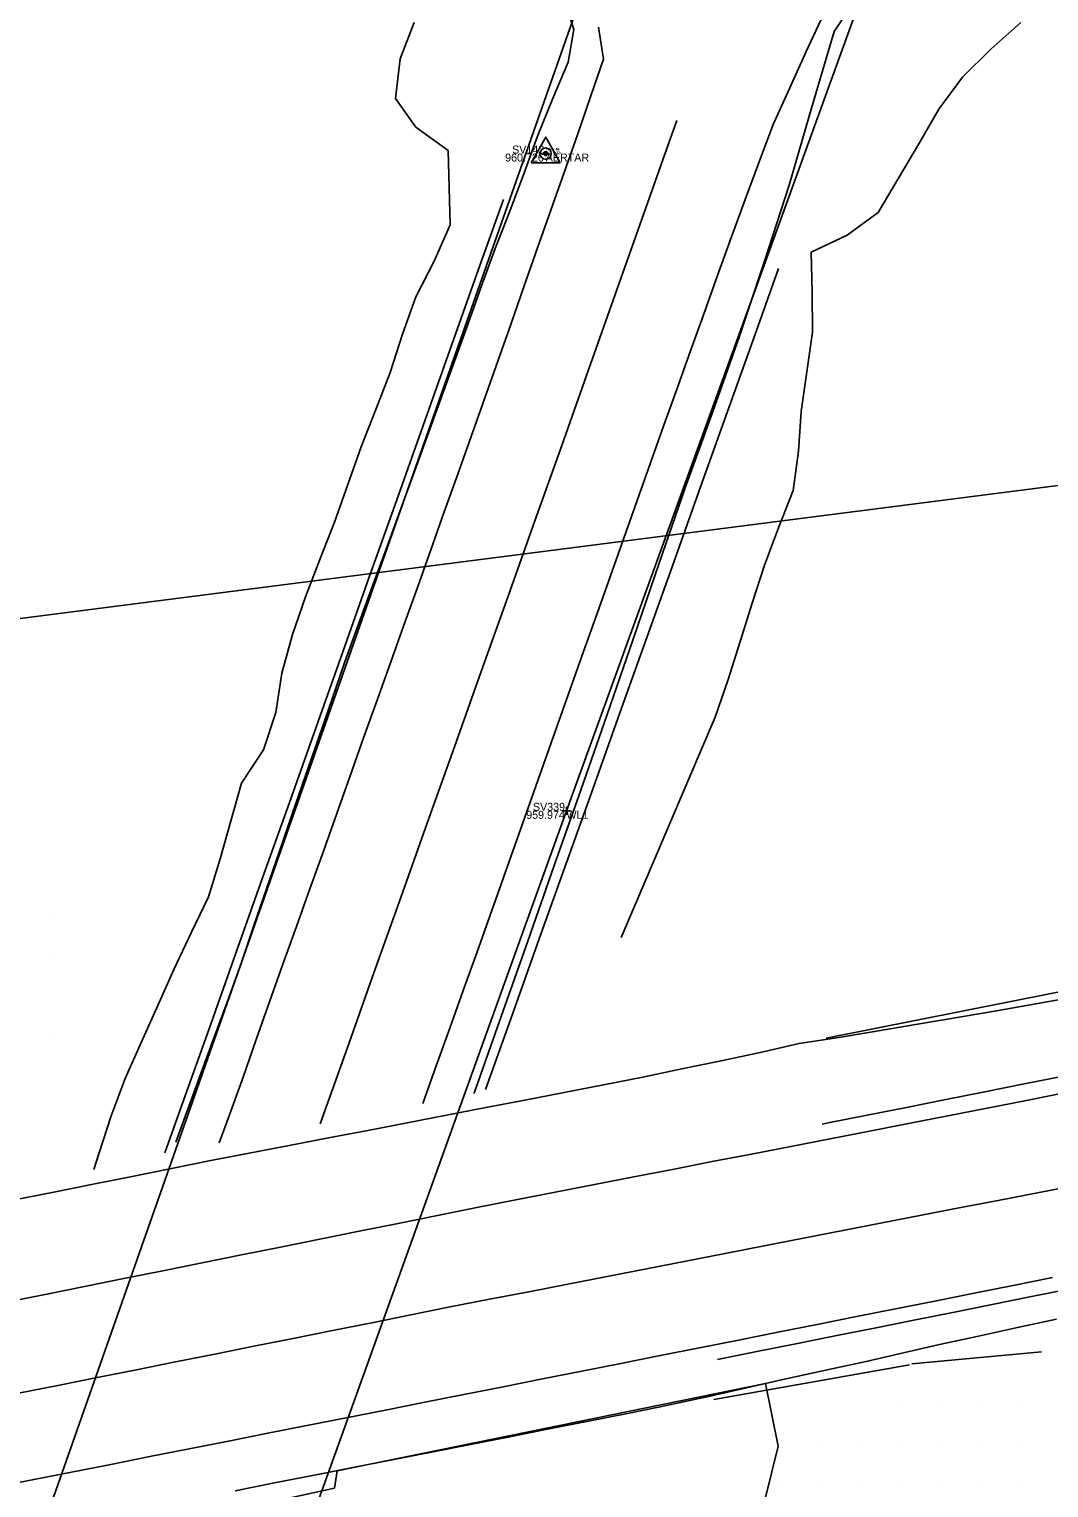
# Model space of a CAD drawing. Extents: x 2262025 to 2264532, y 740981 to 742724.
# Drawn here: x 2263228.5 to 2263355.9, y 742163 to 742345.3 of the extents above; entities that cross this region are included whole.
import ezdxf

# ---------------------------------------------------------------- set-up
doc = ezdxf.new("R2010")
doc.units = 0
for name, color, linetype in [('DT_X_Void', 7, 'Continuous'), ('GE_X_Alignment_1000_Curve_Data', 7, 'Continuous'), ('GE_X_Alignment_100_Bearings', 7, 'Continuous'), ('GE_X_Alignment_100_Cardinal_Points', 7, 'Continuous'), ('GE_X_Alignment_100_Curve_Data', 7, 'Continuous'), ('Ground Shots', 7, 'Continuous'), ('HY_X_Spring_Cells', 7, 'Continuous'), ('RW_X_CL', 7, 'Continuous'), ('RW_X_CL_1000_Bearings', 7, 'Continuous'), ('RW_X_CL_1000_Distances', 7, 'Continuous'), ('RW_X_CL_1000_Stations', 7, 'Continuous'), ('RW_X_CL_100_Cardinal_Points', 7, 'Continuous'), ('RW_X_CL_500_Stations', 7, 'Continuous'), ('SC_Scratch2', 7, 'Continuous'), ('SC_Scratch4', 7, 'Continuous'), ('SV_X_Control_Cells_Found', 7, 'Continuous'), ('SV_X_Text_Comment', 7, 'Continuous'), ('UT_X_Gas', 7, 'Continuous'), ('UT_X_Water', 7, 'Continuous')]:
    doc.layers.add(name, color=color, linetype=linetype)

msp = doc.modelspace()

# ---------------------------------------------------------------- linework, layer by layer
at = {"layer": 'DT_X_Void'}
msp.add_lwpolyline([(2263307.26, 742103.15), (2263312.47, 742108.54), (2263312.43, 742128.22), (2263317.18, 742148.27), (2263322.09, 742168.18), (2263320.51, 742176.01), (2263266.96, 742165.11), (2263266.63, 742162.94), (2263260.36, 742161.57), (2263233.77, 742086.56), (2263242.67, 742096.15), (2263256.64, 742091.14), (2263256.25, 742088.84), (2263275.88, 742092.68), (2263285.52, 742094.16), (2263295.38, 742095.74), (2263305.24, 742097.38)], close=True, dxfattribs=at)
at = {"layer": 'GE_X_Alignment_1000_Curve_Data'}
for points in [[(2263357.74, 742214.44), (2263352.84, 742213.47), (2263347.93, 742212.49), (2263343.03, 742211.51), (2263338.12, 742210.53), (2263333.22, 742209.56), (2263328.32, 742208.58), (2263327.61, 742208.44)], [(2263314.51, 742179.03), (2263319.41, 742180.01), (2263324.32, 742180.99), (2263329.22, 742181.97), (2263334.12, 742182.95), (2263339.03, 742183.93), (2263343.93, 742184.91), (2263348.83, 742185.89), (2263353.74, 742186.87), (2263358.64, 742187.83)]]:
    msp.add_lwpolyline(points, dxfattribs=at)
at = {"layer": 'GE_X_Alignment_100_Bearings'}
for p, q in [((2263338.79, 742178.49), (2263355, 742179.98)), ((2263314.07, 742174.03), (2263338.52, 742178.36))]:
    msp.add_line(p, q, dxfattribs=at)
for points in [[(2263287.76, 742324.03), (2263284.41, 742314.6), (2263281.07, 742305.18), (2263277.72, 742295.76), (2263274.38, 742286.33), (2263271.03, 742276.91), (2263267.69, 742267.48), (2263264.34, 742258.06), (2263261, 742248.64), (2263257.65, 742239.21), (2263254.31, 742229.79), (2263250.96, 742220.36), (2263247.62, 742210.94), (2263245.45, 742204.84)], [(2263285.51, 742212.76), (2263288.87, 742222.18), (2263292.23, 742231.6), (2263295.6, 742241.02), (2263298.96, 742250.44), (2263302.32, 742259.85), (2263305.68, 742269.27), (2263309.04, 742278.69), (2263312.4, 742288.11), (2263315.77, 742297.53), (2263319.13, 742306.94), (2263322.14, 742315.4)]]:
    msp.add_lwpolyline(points, dxfattribs=at)
at = {"layer": 'GE_X_Alignment_100_Cardinal_Points'}
msp.add_lwpolyline([(2263328.11, 742219.18), (2263402.15, 742233.89), (2263485.21, 742250.04), (2263528.29, 742258.28), (2263557.73, 742264.97), (2263579.88, 742270.58), (2263590.62, 742273.55), (2263602.77, 742276.39), (2263620.53, 742279.84), (2263656.59, 742286.79), (2263668.47, 742288.55)], dxfattribs=at)
at = {"layer": 'GE_X_Alignment_100_Curve_Data'}
for points in [[(2263334.36, 742353), (2263329.09, 742345), (2263326.27, 742335.41), (2263323.47, 742325.81), (2263320.4, 742316.3), (2263317.23, 742306.81), (2263313.88, 742297.39), (2263310.48, 742287.98), (2263307.21, 742278.54), (2263303.97, 742269.07), (2263300.7, 742259.62), (2263297.41, 742250.18), (2263294.08, 742240.75), (2263290.79, 742231.31), (2263287.49, 742221.87), (2263284.14, 742212.45), (2263284.07, 742212.25)], [(2263246.8, 742206.18), (2263249.77, 742214.3), (2263251.49, 742218.99), (2263253.22, 742223.69), (2263254.92, 742228.39), (2263256.54, 742233.12), (2263258.16, 742237.85), (2263259.79, 742242.57), (2263261.41, 742247.3), (2263263.04, 742252.03), (2263264.67, 742256.76), (2263266.31, 742261.48), (2263267.94, 742266.21), (2263269.65, 742270.91), (2263271.36, 742275.6), (2263273.08, 742280.3), (2263274.8, 742285), (2263276.52, 742289.69), (2263278.22, 742294.39), (2263279.93, 742299.09), (2263281.63, 742303.79), (2263283.33, 742308.49), (2263285.03, 742313.2), (2263286.74, 742317.9), (2263288.57, 742322.55), (2263290.32, 742327.23), (2263292.03, 742331.93), (2263293.9, 742336.56), (2263295.86, 742341.16), (2263296.57, 742345.24), (2263295.06, 742349.99)], [(2263226.66, 742198.96), (2263231.56, 742199.94), (2263236.47, 742200.92), (2263241.37, 742201.91), (2263246.27, 742202.89), (2263251.17, 742203.87), (2263257.07, 742205.01), (2263260.99, 742205.77), (2263265.9, 742206.71), (2263270.81, 742207.66), (2263275.72, 742208.61), (2263280.63, 742209.55), (2263285.54, 742210.5), (2263290.45, 742211.45), (2263295.36, 742212.39), (2263300.27, 742213.34), (2263305.17, 742214.32), (2263310.07, 742215.34), (2263314.96, 742216.36), (2263319.86, 742217.38), (2263324.71, 742218.53), (2263329.66, 742219.25), (2263334.14, 742220), (2263339.52, 742220.91), (2263342.74, 742221.46), (2263349.37, 742222.6), (2263354.3, 742223.48), (2263359.22, 742224.36)], [(2263356.89, 742184.07), (2263352, 742183.03), (2263347.12, 742181.95), (2263342.24, 742180.88), (2263337.37, 742179.76), (2263333.1, 742178.78), (2263328.79, 742177.84), (2263322.89, 742176.56), (2263318.13, 742175.47), (2263313.59, 742174.42), (2263307.34, 742173.1), (2263303.28, 742172.25), (2263298.37, 742171.29), (2263293.46, 742170.33), (2263288.56, 742169.36), (2263283.65, 742168.39), (2263278.75, 742167.42), (2263273.84, 742166.46), (2263268.94, 742165.5), (2263264.98, 742164.72), (2263259.13, 742163.58), (2263254.22, 742162.62)]]:
    msp.add_lwpolyline(points, dxfattribs=at)
at = {"layer": 'Ground Shots'}
for p, q in [((2263231.3, 742234.59), (2263231.3, 742234.59)), ((2263231.39, 742229.42), (2263231.39, 742229.42)), ((2263231.34, 742219.35), (2263231.34, 742219.35)), ((2263337.49, 742173.05), (2263337.49, 742173.05)), ((2263342.25, 742173.28), (2263342.25, 742173.28)), ((2263347.18, 742173.24), (2263347.18, 742173.24)), ((2263352.21, 742173.09), (2263352.21, 742173.09)), ((2263322.09, 742168.18), (2263322.09, 742168.18)), ((2263327.17, 742168.26), (2263327.17, 742168.26)), ((2263332.18, 742168.18), (2263332.18, 742168.18)), ((2263337.17, 742168.25), (2263337.17, 742168.25)), ((2263342.07, 742168.22), (2263342.07, 742168.22)), ((2263347.09, 742168.26), (2263347.09, 742168.26)), ((2263352.15, 742168.25), (2263352.15, 742168.25)), ((2263322.2, 742163.26), (2263322.2, 742163.26)), ((2263327.11, 742163.23), (2263327.11, 742163.23)), ((2263332.07, 742163.31), (2263332.07, 742163.31)), ((2263337.11, 742163.24), (2263337.11, 742163.24)), ((2263342.13, 742163.28), (2263342.13, 742163.28)), ((2263347.18, 742163.21), (2263347.18, 742163.21)), ((2263352.12, 742163.09), (2263352.12, 742163.09))]:
    msp.add_line(p, q, dxfattribs=at)
at = {"layer": 'RW_X_CL_1000_Bearings'}
msp.add_line((2263293.04, 742329.75), (2263293.04, 742329.75), dxfattribs=at)
msp.add_line((2263293.04, 742329.75), (2263293.04, 742329.75), dxfattribs=at)
msp.add_line((2263293.04, 742329.75), (2263293.04, 742329.75), dxfattribs=at)
msp.add_lwpolyline([(2263291.24, 742328.59), (2263294.84, 742328.59), (2263293.04, 742331.81)], close=True, dxfattribs=at)
for radius in [0.7, 0.16]:
    msp.add_circle((2263293.04, 742329.75), radius, dxfattribs=at)
at = {"layer": 'RW_X_CL_1000_Distances'}
for points in [[(2263277.69, 742211), (2263279.37, 742215.71), (2263281.06, 742220.41), (2263282.74, 742225.12), (2263284.42, 742229.83), (2263286.1, 742234.54), (2263287.77, 742239.25), (2263289.44, 742243.97), (2263291.11, 742248.68), (2263292.77, 742253.39), (2263294.44, 742258.11), (2263296.11, 742262.82), (2263297.78, 742267.53), (2263299.45, 742272.25), (2263301.12, 742276.96), (2263302.8, 742281.67), (2263304.47, 742286.38), (2263306.15, 742291.09), (2263307.82, 742295.8), (2263309.5, 742300.51), (2263311.18, 742305.22), (2263312.88, 742309.92), (2263314.57, 742314.63), (2263316.27, 742319.33), (2263317.97, 742324.03), (2263319.72, 742328.72), (2263321.48, 742333.4), (2263323.53, 742337.96), (2263325.59, 742342.51), (2263327.72, 742347.03)], [(2263299.62, 742345.53), (2263300.25, 742341.56)], [(2263300.25, 742341.56), (2263298.63, 742336.83), (2263297.01, 742332.1), (2263295.35, 742327.38), (2263293.67, 742322.67), (2263292.01, 742317.95), (2263290.36, 742313.23), (2263288.71, 742308.52), (2263287.05, 742303.8), (2263285.38, 742299.09), (2263283.71, 742294.37), (2263282.04, 742289.66), (2263280.36, 742284.95), (2263278.68, 742280.24), (2263277, 742275.53), (2263275.32, 742270.82), (2263273.64, 742266.11), (2263271.96, 742261.41), (2263270.28, 742256.7), (2263268.6, 742251.99), (2263266.92, 742247.28), (2263265.25, 742242.56), (2263263.57, 742237.85), (2263261.89, 742233.14), (2263260.2, 742228.44), (2263258.51, 742223.73), (2263256.85, 742219.02), (2263255.23, 742214.29), (2263253.53, 742209.59), (2263252.25, 742206.08)], [(2263225.6, 742186.17), (2263230.5, 742187.15), (2263235.4, 742188.14), (2263240.3, 742189.12), (2263245.21, 742190.1), (2263250.11, 742191.09), (2263255.01, 742192.08), (2263259.91, 742193.07), (2263264.81, 742194.05), (2263269.71, 742195.04), (2263274.62, 742196.03), (2263279.52, 742197.02), (2263284.42, 742198), (2263289.32, 742198.97), (2263294.23, 742199.93), (2263299.14, 742200.88), (2263304.05, 742201.84), (2263308.89, 742202.78), (2263313.86, 742203.75), (2263318.77, 742204.7), (2263323.68, 742205.65), (2263328.59, 742206.61), (2263333.5, 742207.56), (2263338.4, 742208.52), (2263343.31, 742209.47), (2263348.22, 742210.44), (2263353.13, 742211.4), (2263358.03, 742212.37)], [(2263356.39, 742189.25), (2263351.48, 742188.27), (2263346.58, 742187.3), (2263341.67, 742186.32), (2263336.77, 742185.35), (2263331.87, 742184.38), (2263326.96, 742183.4), (2263322.06, 742182.43), (2263317.15, 742181.45), (2263312.25, 742180.48), (2263307.35, 742179.5), (2263302.44, 742178.53), (2263297.54, 742177.56), (2263292.63, 742176.59), (2263287.73, 742175.62), (2263282.82, 742174.65), (2263277.92, 742173.67), (2263273.01, 742172.7), (2263268.11, 742171.73), (2263263.2, 742170.76), (2263258.3, 742169.79), (2263253.39, 742168.82), (2263248.49, 742167.85), (2263243.58, 742166.88), (2263238.68, 742165.9), (2263233.77, 742164.93), (2263228.87, 742163.97), (2263223.96, 742163.02)]]:
    msp.add_lwpolyline(points, dxfattribs=at)
at = {"layer": 'RW_X_CL_1000_Stations'}
msp.add_line((2263293.04, 742329.75), (2263293.04, 742329.75), dxfattribs=at)
msp.add_line((2263293.04, 742329.75), (2263293.04, 742329.75), dxfattribs=at)
msp.add_line((2263293.04, 742329.75), (2263293.04, 742329.75), dxfattribs=at)
msp.add_circle((2263293.04, 742329.75), 0.25, dxfattribs=at)
msp.add_circle((2263293.04, 742329.75), 0.25, dxfattribs=at)
msp.add_circle((2263293.04, 742329.75), 0.25, dxfattribs=at)
at = {"layer": 'RW_X_CL_100_Cardinal_Points'}
for p, q in [((2263295.63, 742248.1), (2263295.63, 742247.1)), ((2263295.13, 742247.6), (2263296.13, 742247.6)), ((2263295.63, 742247.6), (2263295.63, 742247.6))]:
    msp.add_line(p, q, dxfattribs=at)
at = {"layer": 'RW_X_CL_500_Stations'}
msp.add_line((2263398.72, 742293.58), (2263176.67, 742265.17), dxfattribs=at)
at = {"layer": 'SC_Scratch2'}
msp.add_lwpolyline([(2263359.62, 742200.86), (2263354.72, 742199.91), (2263349.81, 742198.95), (2263344.9, 742198), (2263339.99, 742197.04), (2263335.08, 742196.09), (2263330.18, 742195.13), (2263325.27, 742194.18), (2263320.36, 742193.22), (2263315.45, 742192.27), (2263310.55, 742191.31), (2263305.64, 742190.36), (2263300.73, 742189.4), (2263295.82, 742188.45), (2263290.91, 742187.49), (2263286.01, 742186.54), (2263281.1, 742185.58), (2263276.19, 742184.6), (2263271.29, 742183.62), (2263266.39, 742182.64), (2263261.49, 742181.66), (2263256.58, 742180.68), (2263251.68, 742179.7), (2263246.78, 742178.72), (2263241.88, 742177.73), (2263236.97, 742176.75), (2263232.07, 742175.77), (2263227.17, 742174.79)], dxfattribs=at)
at = {"layer": 'SC_Scratch4'}
msp.add_lwpolyline([(2263264.87, 742208.49), (2263268.22, 742217.91), (2263271.57, 742227.33), (2263274.92, 742236.75), (2263278.27, 742246.17), (2263281.62, 742255.59), (2263284.98, 742265.01), (2263288.34, 742274.43), (2263291.69, 742283.85), (2263295.05, 742293.27), (2263298.4, 742302.7), (2263301.73, 742312.12), (2263305.07, 742321.55), (2263308.4, 742330.98), (2263309.43, 742333.89)], dxfattribs=at)
at = {"layer": 'SV_X_Control_Cells_Found'}
for points in [[(2263276.61, 742346.13), (2263274.87, 742341.59), (2263274.25, 742336.64), (2263276.81, 742333.06), (2263280.85, 742330.12), (2263281.1, 742320.85), (2263279.1, 742316.31), (2263276.82, 742311.86), (2263275.15, 742307.16), (2263273.61, 742302.4), (2263271.8, 742297.75), (2263269.98, 742293.09), (2263268.33, 742288.37), (2263266.63, 742283.67), (2263264.81, 742279.01), (2263263.03, 742274.34), (2263261.38, 742269.62), (2263260.07, 742264.81), (2263259.31, 742259.87), (2263257.77, 742255.23), (2263255.04, 742251.05), (2263252.37, 742241.59), (2263250.9, 742236.86), (2263248.73, 742232.36), (2263246.62, 742227.83), (2263244.56, 742223.28), (2263242.52, 742218.71), (2263240.5, 742214.14), (2263238.75, 742209.47), (2263237.19, 742204.73), (2263236.55, 742202.78)], [(2263352.41, 742346.12), (2263348.68, 742342.8), (2263345.14, 742339.28), (2263342.19, 742335.3), (2263339.69, 742330.96), (2263337.15, 742326.66), (2263334.58, 742322.37), (2263330.7, 742319.54), (2263326.21, 742317.41), (2263326.34, 742312.42), (2263326.4, 742307.43), (2263324.96, 742297.53), (2263324.63, 742292.55), (2263323.96, 742287.64), (2263322.13, 742282.98), (2263320.38, 742278.3), (2263318.86, 742273.54), (2263317.35, 742268.78), (2263315.83, 742264.03), (2263314.22, 742259.31), (2263312.26, 742254.71), (2263304.43, 742236.36), (2263302.48, 742231.77)]]:
    msp.add_lwpolyline(points, dxfattribs=at)
at = {"layer": 'UT_X_Gas'}
msp.add_lwpolyline([(2263370.65, 742558.56), (2263358.32, 742523.53), (2263332.75, 742449.83), (2263131.85, 741878.34), (2263108.26, 741811.62)], dxfattribs=at)
at = {"layer": 'UT_X_Water'}
msp.add_lwpolyline([(2263058.18, 741572.97), (2263085.82, 741651.25), (2263095.93, 741679.99), (2263097.95, 741685.82), (2263106.82, 741712.78), (2263147.36, 741828.66), (2263178.07, 741920.18), (2263217.98, 742032.49), (2263252.6, 742127.99), (2263295.63, 742247.6), (2263334.95, 742356.22), (2263370.78, 742449.55), (2263413.67, 742573.04), (2263421.38, 742593.43)], dxfattribs=at)

# ---------------------------------------------------------------- texts
at = {"layer": 'HY_X_Spring_Cells'}
for s, p in [('960.726', (2263287.97, 742328.75)), ('959.974', (2263290.6, 742246.6))]:
    msp.add_text(s, height=1, dxfattribs=at).set_placement(p)
at = {"layer": 'RW_X_CL'}
for s, p in [('AERTAR', (2263293.04, 742328.75)), ('WL1', (2263295.63, 742246.6))]:
    msp.add_text(s, height=1, dxfattribs=at).set_placement(p)
at = {"layer": 'RW_X_CL_1000_Stations'}
for s, p in [('Index: 49', (2263293.04, 742330.15)), ('Index: 58', (2263293.04, 742330.15)), ('Index: 67', (2263293.04, 742330.15)), ('ΔZ: -0.005', (2263293.04, 742329.75)), ('ΔZ: -0.005', (2263293.04, 742329.75)), ('ΔZ: -0.005', (2263293.04, 742329.75))]:
    msp.add_text(s, height=0.3, dxfattribs=at).set_placement(p)
at = {"layer": 'SV_X_Text_Comment'}
for s, p in [('SV142', (2263288.84, 742329.75)), ('SV339', (2263291.44, 742247.6))]:
    msp.add_text(s, height=1, dxfattribs=at).set_placement(p)

doc.saveas('drawing.dxf')
